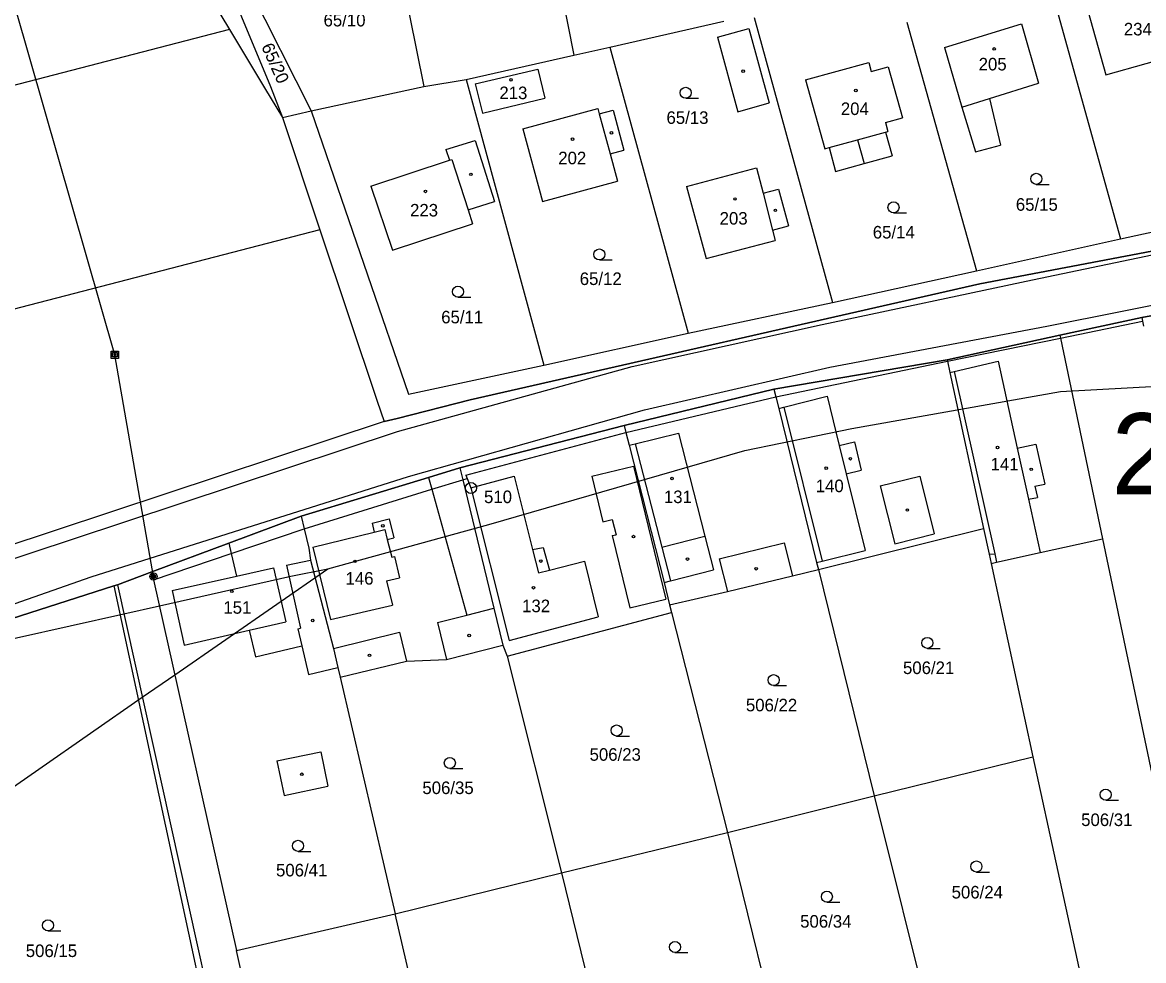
# Model space of a CAD drawing. Extents: x -725765 to -723182, y -1052705 to -1049154.
# Drawn here: x -724986 to -724834.1, y -1051208.1 to -1051081 of the extents above; entities that cross this region are included whole.
import ezdxf

# ---------------------------------------------------------------- set-up
doc = ezdxf.new("R2010")
doc.units = 0
for name, color, linetype in [('Vrstva 1', 7, 'Continuous'), ('Vrstva 12', 7, 'Continuous'), ('Vrstva 17', 7, 'Continuous'), ('Vrstva 18', 7, 'Continuous'), ('Vrstva 19', 7, 'Continuous'), ('Vrstva 25', 7, 'Continuous'), ('Vrstva 4', 7, 'Continuous'), ('Vrstva 52', 7, 'Continuous'), ('Vrstva 53', 7, 'Continuous')]:
    doc.layers.add(name, color=color, linetype=linetype)

msp = doc.modelspace()

# ---------------------------------------------------------------- linework, layer by layer
at = {"layer": 'Vrstva 1'}
for points in [[(-724918.87, -1051047.1), (-724911.27, -1051085.47)], [(-724939.3, -1051051.63), (-724931.61, -1051089.72)], [(-724963.58, -1051059.89), (-724946.87, -1051092.99)], [(-724960.47, -1051070.23), (-724952.37, -1051089.69)], [(-724964.46, -1051071.2), (-724957.95, -1051081.99)], [(-724847.95, -1051071.78), (-724837.23, -1051110.34)], [(-724842.01, -1051078.13), (-724839.24, -1051088.1)], [(-724906.4, -1051084.35), (-724890.95, -1051080.83)], [(-724886.87, -1051080.34), (-724876.24, -1051118.93)], [(-724866.18, -1051080.99), (-724856.76, -1051114.67)], [(-724861.08, -1051084.41), (-724850.66, -1051081.22)], [(-724850.66, -1051081.22), (-724848.32, -1051089.26)], [(-724957.95, -1051081.99), (-725181.44, -1051139.93)], [(-724957.95, -1051081.99), (-724953.19, -1051089.88), (-724950.77, -1051093.89)], [(-724911.27, -1051085.47), (-724906.4, -1051084.35)], [(-724906.4, -1051084.35), (-724895.82, -1051123.1)], [(-724925.9, -1051088.74), (-724911.27, -1051085.47)], [(-724861.08, -1051084.41), (-724858.73, -1051092.49)], [(-724839.24, -1051088.1), (-724828.29, -1051085.04)], [(-724924.64, -1051089.34), (-724916.16, -1051087.33)], [(-724916.16, -1051087.33), (-724915.23, -1051091.27)], [(-724879.9, -1051088.81), (-724871.34, -1051086.45)], [(-724871.34, -1051086.45), (-724871.02, -1051087.66)], [(-724871.02, -1051087.66), (-724868.72, -1051087.05)], [(-724868.72, -1051087.05), (-724866.77, -1051093.94)], [(-724931.61, -1051089.72), (-724925.9, -1051088.74)], [(-724925.9, -1051088.74), (-724915.34, -1051127.42)], [(-724879.9, -1051088.81), (-724877.3, -1051098.14)], [(-724952.37, -1051089.69), (-724950.77, -1051093.89)], [(-724946.87, -1051092.99), (-724931.61, -1051089.72)], [(-724924.64, -1051089.34), (-724923.67, -1051093.3)], [(-724855, -1051091.33), (-724848.32, -1051089.26)], [(-724923.67, -1051093.3), (-724915.23, -1051091.27)], [(-724855, -1051091.33), (-724853.47, -1051097.65)], [(-724950.77, -1051093.89), (-724946.87, -1051092.99)], [(-724946.87, -1051092.99), (-724939.23, -1051115.22)], [(-724918.18, -1051095.44), (-724908.03, -1051092.69)], [(-724908.03, -1051092.69), (-724907.84, -1051093.4)], [(-724907.84, -1051093.4), (-724905.98, -1051092.9)], [(-724905.98, -1051092.9), (-724904.5, -1051098.32)], [(-724858.73, -1051092.49), (-724856.88, -1051098.54)], [(-724950.77, -1051093.89), (-724945.68, -1051109.11)], [(-724869.09, -1051094.58), (-724866.77, -1051093.94)], [(-724869.09, -1051094.58), (-724868.76, -1051095.79)], [(-724918.18, -1051095.44), (-724915.53, -1051105.26)], [(-724869.05, -1051095.87), (-724868.76, -1051095.79)], [(-724869.05, -1051095.87), (-724868.17, -1051099.08)], [(-724928.62, -1051098.25), (-724924.67, -1051097.02)], [(-724924.67, -1051097.02), (-724922.03, -1051105.26)], [(-724877.3, -1051098.14), (-724876.72, -1051097.98)], [(-724876.72, -1051097.98), (-724875.84, -1051101.19)], [(-724856.88, -1051098.54), (-724853.47, -1051097.65)], [(-724928.62, -1051098.25), (-724928.15, -1051099.69)], [(-724906.36, -1051098.82), (-724904.5, -1051098.32)], [(-724906.36, -1051098.82), (-724905.36, -1051102.51)], [(-724871.98, -1051100.13), (-724868.17, -1051099.08)], [(-724938.78, -1051103.21), (-724928.15, -1051099.69)], [(-724896.03, -1051103.25), (-724886.54, -1051100.73)], [(-724886.54, -1051100.73), (-724885.65, -1051104.15)], [(-724875.84, -1051101.19), (-724871.98, -1051100.13)], [(-724915.53, -1051105.26), (-724905.36, -1051102.51)], [(-724938.78, -1051103.21), (-724935.84, -1051111.84)], [(-724896.03, -1051103.25), (-724893.36, -1051113.01)], [(-724885.65, -1051104.15), (-724883.57, -1051103.6)], [(-724883.57, -1051103.6), (-724882.22, -1051108.57)], [(-724925.59, -1051106.41), (-724922.03, -1051105.26)], [(-724925.59, -1051106.41), (-724925, -1051108.28)], [(-724837.23, -1051110.34), (-724817.68, -1051106.09)], [(-724935.84, -1051111.84), (-724925, -1051108.28)], [(-724884.36, -1051109.16), (-724882.22, -1051108.57)], [(-724945.68, -1051109.11), (-725175.46, -1051168.68)], [(-724945.68, -1051109.11), (-724937.92, -1051132.29)], [(-724884.36, -1051109.16), (-724884, -1051110.53)], [(-724856.27, -1051116.41), (-724816.84, -1051108.91)], [(-724893.36, -1051113.01), (-724884, -1051110.53)], [(-724856.76, -1051114.67), (-724837.23, -1051110.34)], [(-724876.24, -1051118.93), (-724856.76, -1051114.67)], [(-724939.23, -1051115.22), (-724933.68, -1051131.38)], [(-724925.34, -1051132.13), (-724856.27, -1051116.41)], [(-724834.36, -1051120.96), (-724811.15, -1051116.69)], [(-724895.82, -1051123.1), (-724876.24, -1051118.93)], [(-724845.44, -1051123.38), (-724834.36, -1051120.96)], [(-724834.36, -1051120.96), (-724834.26, -1051121.49)], [(-724834.26, -1051121.49), (-724834.1, -1051122.17)], [(-724915.34, -1051127.42), (-724895.82, -1051123.1)], [(-724860.72, -1051126.71), (-724845.44, -1051123.38)], [(-724845.44, -1051123.38), (-724845.36, -1051123.76)], [(-724845.36, -1051123.76), (-724839.66, -1051150.93)], [(-724884.18, -1051130.69), (-724860.72, -1051126.71)], [(-724860.72, -1051126.71), (-724860.68, -1051126.9)], [(-724860.68, -1051126.9), (-724860.35, -1051128.42)], [(-724933.68, -1051131.38), (-724915.34, -1051127.42)], [(-724860.35, -1051128.42), (-724855.78, -1051149.55)], [(-724904.47, -1051135.61), (-724884.18, -1051130.69)], [(-724884.18, -1051130.69), (-724883.92, -1051131.73)], [(-724937.92, -1051132.29), (-724936.98, -1051135.08)], [(-724935.23, -1051134.64), (-724925.34, -1051132.13)], [(-724883.92, -1051131.73), (-724883.54, -1051133.28)], [(-724883.54, -1051133.28), (-724878.4, -1051154.14)], [(-724936.98, -1051135.08), (-725011.19, -1051159.63)], [(-724936.98, -1051135.08), (-724935.23, -1051134.64)], [(-724926.75, -1051141.34), (-724904.47, -1051135.61)], [(-724904.47, -1051135.61), (-724904.23, -1051136.57)], [(-724904.23, -1051136.57), (-724903.79, -1051138.28)], [(-724903.79, -1051138.28), (-724899.07, -1051156.87)], [(-724930.97, -1051142.63), (-724926.75, -1051141.34)], [(-724926.75, -1051141.34), (-724926.34, -1051142.94)], [(-724948.22, -1051147.9), (-724930.97, -1051142.63)], [(-724930.97, -1051142.63), (-724930.52, -1051144.24)], [(-724926.34, -1051142.94), (-724922.12, -1051160.36)], [(-724930.52, -1051144.24), (-724925.8, -1051161.28)], [(-724958.02, -1051151.55), (-724948.22, -1051147.9)], [(-724948.22, -1051147.9), (-724947.82, -1051149.61)], [(-724947.82, -1051149.61), (-724947.2, -1051152.23)], [(-724878.16, -1051155.11), (-724855.78, -1051149.55)], [(-724855.78, -1051149.55), (-724855.03, -1051153.04)], [(-724848.12, -1051152.8), (-724839.66, -1051150.93)], [(-724839.66, -1051150.93), (-724823.81, -1051226.41)], [(-724968.47, -1051155.44), (-724958.02, -1051151.55)], [(-724958.02, -1051151.55), (-724957.7, -1051152.94)], [(-724947.2, -1051152.23), (-724946.95, -1051153.82)], [(-724957.7, -1051152.94), (-724956.98, -1051156)], [(-724946.95, -1051153.82), (-724943.87, -1051165.78)], [(-724878.4, -1051154.14), (-724878.16, -1051155.11)], [(-724855.03, -1051153.04), (-724854.76, -1051154.27)], [(-724854.76, -1051154.27), (-724854.01, -1051154.1)], [(-724854.01, -1051154.1), (-724848.12, -1051152.8)], [(-724973.12, -1051157.17), (-724968.47, -1051155.44)], [(-724968.47, -1051155.44), (-724968.23, -1051156.49)], [(-724881.69, -1051155.97), (-724878.16, -1051155.11)], [(-724878.16, -1051155.11), (-724870.61, -1051185.73)], [(-724854.76, -1051154.27), (-724849.09, -1051180.48)], [(-724973.59, -1051157.32), (-724973.12, -1051157.17)], [(-724973.12, -1051157.17), (-724950.33, -1051260.17)], [(-724968.23, -1051156.49), (-724956.97, -1051206.71)], [(-724965.73, -1051157.96), (-724956.98, -1051156)], [(-724899.07, -1051156.87), (-724898.31, -1051159.87)], [(-724890.48, -1051158.09), (-724881.69, -1051155.97)], [(-725009.19, -1051168.73), (-724973.59, -1051157.32)], [(-724965.73, -1051157.96), (-724964.09, -1051165.34)], [(-724898.31, -1051159.87), (-724890.48, -1051158.09)], [(-724898.31, -1051159.87), (-724898.04, -1051160.94)], [(-724929.77, -1051162.27), (-724925.8, -1051161.28)], [(-724922.12, -1051160.36), (-724920.89, -1051165.34)], [(-724920.33, -1051166.83), (-724898.04, -1051160.94)], [(-724898.04, -1051160.94), (-724890.47, -1051190.71)], [(-724964.09, -1051165.34), (-724955.27, -1051163.31)], [(-724955.27, -1051163.31), (-724954.44, -1051166.92)], [(-724929.77, -1051162.27), (-724928.52, -1051167.28)], [(-724954.44, -1051166.92), (-724948.14, -1051165.46)], [(-724948.14, -1051165.46), (-724947.23, -1051169.32)], [(-724943.87, -1051165.78), (-724943.27, -1051168.39)], [(-724920.89, -1051165.34), (-724920.33, -1051166.83)], [(-724942.93, -1051169.69), (-724933.97, -1051167.53)], [(-724933.97, -1051167.53), (-724928.52, -1051167.28)], [(-724920.33, -1051166.83), (-724912.94, -1051196.18)], [(-724947.23, -1051169.32), (-724943.27, -1051168.39)], [(-724943.27, -1051168.39), (-724942.93, -1051169.69)], [(-724942.93, -1051169.69), (-724935.5, -1051201.73)], [(-724870.61, -1051185.73), (-724849.09, -1051180.48)], [(-724849.09, -1051180.48), (-724842.32, -1051211.51)], [(-724890.47, -1051190.71), (-724870.61, -1051185.73)], [(-724870.61, -1051185.73), (-724862.89, -1051216.71)], [(-724912.94, -1051196.18), (-724890.47, -1051190.71)], [(-724890.47, -1051190.71), (-724882.37, -1051223.57)], [(-724935.5, -1051201.73), (-724912.94, -1051196.18)], [(-724912.94, -1051196.18), (-724905.17, -1051228.09)], [(-724956.97, -1051206.71), (-724935.5, -1051201.73)], [(-724929.66, -1051226.78), (-724935.5, -1051201.73)], [(-724951.47, -1051231.54), (-724956.97, -1051206.71)]]:
    msp.add_lwpolyline(points, dxfattribs=at)
at = {"layer": 'Vrstva 12'}
for points in [[(-724973.47, -1051126.02), (-724988.81, -1051072.44)], [(-724968.25, -1051156.05), (-724973.47, -1051126.02)]]:
    msp.add_lwpolyline(points, dxfattribs=at)
at = {"layer": 'Vrstva 25'}
for points in [[(-724896.13, -1051091.3), (-724894.38, -1051091.3)], [(-724848.64, -1051102.95), (-724846.89, -1051102.95)], [(-724867.98, -1051106.81), (-724866.23, -1051106.81)], [(-724907.83, -1051113.19), (-724906.08, -1051113.19)], [(-724926.99, -1051118.24), (-724925.24, -1051118.24)], [(-724973.97, -1051125.52), (-724972.97, -1051125.52), (-724972.97, -1051126.52), (-724973.97, -1051126.52), (-724973.97, -1051125.52)], [(-724973.77, -1051125.72), (-724973.17, -1051125.72), (-724973.17, -1051126.32), (-724973.77, -1051126.32), (-724973.77, -1051125.72)], [(-724973.57, -1051125.92), (-724973.37, -1051125.92), (-724973.37, -1051126.12), (-724973.57, -1051126.12), (-724973.57, -1051125.92)], [(-724863.4, -1051165.79), (-724861.65, -1051165.79)], [(-724884.23, -1051170.83), (-724882.48, -1051170.83)], [(-724905.49, -1051177.65), (-724903.74, -1051177.65)], [(-724928.09, -1051182.05), (-724926.34, -1051182.05)], [(-724839.24, -1051186.34), (-724837.49, -1051186.34)], [(-724948.65, -1051193.27), (-724946.9, -1051193.27)], [(-724856.75, -1051196.07), (-724855, -1051196.07)], [(-724877.01, -1051200.16), (-724875.26, -1051200.16)], [(-724982.54, -1051204.04), (-724980.79, -1051204.04)], [(-724897.59, -1051206.97), (-724895.84, -1051206.97)]]:
    msp.add_lwpolyline(points, dxfattribs=at)
for centre, radius in [((-724854.35, -1051084.61), 0.175), ((-724919.8, -1051088.79), 0.175), ((-724888.35, -1051087.63), 0.175), ((-724896.13, -1051090.55), 0.75), ((-724873.08, -1051090.25), 0.175), ((-724906.2, -1051095.97), 0.175), ((-724911.46, -1051096.84), 0.175), ((-724925.23, -1051101.59), 0.175), ((-724848.64, -1051102.2), 0.75), ((-724931.4, -1051103.9), 0.175), ((-724889.46, -1051104.93), 0.175), ((-724867.98, -1051106.06), 0.75), ((-724883.99, -1051106.47), 0.175), ((-724907.83, -1051112.44), 0.75), ((-724926.99, -1051117.49), 0.75), ((-724853.88, -1051138.59), 0.175), ((-724873.83, -1051140.1), 0.175), ((-724877.09, -1051141.39), 0.175), ((-724849.32, -1051141.54), 0.175), ((-724925.23, -1051144.06), 0.75), ((-724897.99, -1051142.77), 0.175), ((-724925.23, -1051144.06), 0.032), ((-724866.11, -1051147.05), 0.175), ((-724937.16, -1051149.18), 0.175), ((-724903.2, -1051150.65), 0.175), ((-724940.94, -1051154), 0.175), ((-724915.76, -1051153.96), 0.175), ((-724895.9, -1051153.69), 0.175), ((-724968.25, -1051156.05), 0.5), ((-724968.25, -1051156.05), 0.3), ((-724886.58, -1051155), 0.175), ((-724968.25, -1051156.05), 0.15), ((-724957.61, -1051158.05), 0.175), ((-724916.75, -1051157.57), 0.175), ((-724946.67, -1051162), 0.175), ((-724925.47, -1051164.03), 0.175), ((-724863.4, -1051165.04), 0.75), ((-724938.97, -1051166.73), 0.175), ((-724884.23, -1051170.08), 0.75), ((-724905.49, -1051176.9), 0.75), ((-724928.09, -1051181.3), 0.75), ((-724948.14, -1051182.83), 0.175), ((-724839.24, -1051185.59), 0.75), ((-724948.65, -1051192.52), 0.75), ((-724856.75, -1051195.32), 0.75), ((-724877.01, -1051199.41), 0.75), ((-724982.54, -1051203.29), 0.75), ((-724897.59, -1051206.22), 0.75)]:
    msp.add_circle(centre, radius, dxfattribs=at)
at = {"layer": 'Vrstva 4'}
for points in [[(-724891.81, -1051083.01), (-724887.57, -1051081.86)], [(-724887.57, -1051081.86), (-724884.83, -1051091.93)], [(-724891.81, -1051083.01), (-724889.06, -1051093.11)], [(-724889.06, -1051093.11), (-724884.83, -1051091.93)], [(-724858.73, -1051092.49), (-724855, -1051091.33)], [(-724907.84, -1051093.4), (-724906.36, -1051098.82)], [(-724872.86, -1051096.92), (-724869.05, -1051095.87)], [(-724876.72, -1051097.98), (-724872.86, -1051096.92)], [(-724872.86, -1051096.92), (-724871.98, -1051100.13)], [(-724928.15, -1051099.69), (-724927.81, -1051099.58)], [(-724927.81, -1051099.58), (-724925.59, -1051106.41)], [(-724885.65, -1051104.15), (-724884.36, -1051109.16)], [(-724849.16, -1051115.88), (-724818.67, -1051109.51)], [(-724877.64, -1051121.92), (-724849.16, -1051115.88)], [(-724847.23, -1051122.13), (-724816.84, -1051116.09)], [(-724903.4, -1051127.62), (-724877.64, -1051121.92)], [(-724876.62, -1051127.71), (-724847.23, -1051122.13)], [(-724845.36, -1051123.76), (-724834.26, -1051121.49)], [(-724860.68, -1051126.9), (-724845.36, -1051123.76)], [(-724883.92, -1051131.73), (-724860.68, -1051126.9)], [(-724859.76, -1051128.28), (-724853.79, -1051126.9)], [(-724853.79, -1051126.9), (-724851.21, -1051138.68)], [(-724935.17, -1051136.41), (-724903.4, -1051127.62)], [(-724901.71, -1051133.46), (-724876.62, -1051127.71)], [(-724860.35, -1051128.42), (-724859.76, -1051128.28)], [(-724859.76, -1051128.28), (-724854.26, -1051152.99)], [(-724904.23, -1051136.57), (-724883.92, -1051131.73)], [(-724882.84, -1051133.11), (-724876.98, -1051131.64)], [(-724876.98, -1051131.64), (-724875.33, -1051138.32)], [(-724933.69, -1051142.51), (-724901.71, -1051133.46)], [(-724883.54, -1051133.28), (-724882.84, -1051133.11)], [(-724882.84, -1051133.11), (-724877.67, -1051153.96)], [(-724979.2, -1051151.01), (-724935.17, -1051136.41)], [(-724925.91, -1051142.34), (-724904.23, -1051136.57)], [(-724902.97, -1051138.08), (-724897.1, -1051136.62)], [(-724897.1, -1051136.62), (-724893.53, -1051150.58)], [(-724903.79, -1051138.28), (-724902.97, -1051138.08)], [(-724902.97, -1051138.08), (-724899.38, -1051152.06)], [(-724875.33, -1051138.32), (-724873.28, -1051137.82)], [(-724875.33, -1051138.32), (-724874.39, -1051142.15)], [(-724873.28, -1051137.82), (-724872.37, -1051141.63)], [(-724851.21, -1051138.68), (-724848.69, -1051138.14)], [(-724851.21, -1051138.68), (-724849.7, -1051145.6)], [(-724848.69, -1051138.14), (-724847.5, -1051143.53)], [(-724908.86, -1051142.48), (-724903.23, -1051141.09)], [(-724903.23, -1051141.09), (-724898.84, -1051159.11)], [(-724874.39, -1051142.15), (-724872.37, -1051141.63)], [(-724976.7, -1051156.09), (-724933.69, -1051142.51)], [(-724930.52, -1051144.24), (-724926.34, -1051142.94)], [(-724926.34, -1051142.94), (-724925.76, -1051142.78)], [(-724925.91, -1051142.34), (-724925.76, -1051142.78)], [(-724925.76, -1051142.78), (-724925.23, -1051144.06)], [(-724925.23, -1051144.06), (-724919.36, -1051142.48)], [(-724919.36, -1051142.48), (-724916.87, -1051152.4)], [(-724908.86, -1051142.48), (-724907.35, -1051148.63)], [(-724874.39, -1051142.15), (-724871.84, -1051152.51)], [(-724869.78, -1051143.75), (-724864.43, -1051142.45)], [(-724864.43, -1051142.45), (-724862.48, -1051150.29)], [(-724848.82, -1051143.82), (-724847.5, -1051143.53)], [(-724947.82, -1051149.61), (-724930.52, -1051144.24)], [(-724925.23, -1051144.06), (-724920.07, -1051164.7)], [(-724869.78, -1051143.75), (-724867.82, -1051151.62)], [(-724848.82, -1051143.82), (-724848.47, -1051145.36)], [(-724849.7, -1051145.6), (-724848.47, -1051145.36)], [(-724849.7, -1051145.6), (-724848.12, -1051152.8)], [(-724957.7, -1051152.94), (-724947.82, -1051149.61)], [(-724938.63, -1051148.81), (-724936.33, -1051148.26)], [(-724938.63, -1051148.81), (-724938.32, -1051150.05)], [(-724936.33, -1051148.26), (-724935.69, -1051150.83)], [(-724907.35, -1051148.63), (-724906.08, -1051148.32)], [(-724906.08, -1051148.32), (-724905.57, -1051150.39)], [(-725010.8, -1051161.4), (-724979.2, -1051151.01)], [(-724946.63, -1051152.09), (-724938.32, -1051150.05)], [(-724938.32, -1051150.05), (-724936.91, -1051149.7)], [(-724936.91, -1051149.7), (-724936.57, -1051151.06)], [(-724936.57, -1051151.06), (-724935.69, -1051150.83)], [(-724936.57, -1051151.06), (-724935.96, -1051153.45)], [(-724906.11, -1051150.52), (-724905.57, -1051150.39)], [(-724906.11, -1051150.52), (-724903.7, -1051160.31)], [(-724899.38, -1051152.06), (-724893.53, -1051150.58)], [(-724893.53, -1051150.58), (-724892.36, -1051155.16)], [(-724867.82, -1051151.62), (-724862.48, -1051150.29)], [(-724946.63, -1051152.09), (-724944.25, -1051161.89)], [(-724916.87, -1051152.4), (-724915.43, -1051152.11)], [(-724916.87, -1051152.4), (-724916.07, -1051155.57)], [(-724915.43, -1051152.11), (-724914.6, -1051155.19)], [(-724899.38, -1051152.06), (-724898.2, -1051156.65)], [(-724891.59, -1051153.66), (-724882.8, -1051151.48)], [(-724882.8, -1051151.48), (-724881.69, -1051155.97)], [(-724877.67, -1051153.96), (-724871.84, -1051152.51)], [(-724968.23, -1051156.49), (-724957.7, -1051152.94)], [(-724950.21, -1051154.52), (-724946.95, -1051153.82)], [(-724935.96, -1051153.45), (-724935.6, -1051153.36)], [(-724935.6, -1051153.36), (-724934.89, -1051156.22)], [(-724914.6, -1051155.19), (-724909.84, -1051153.96)], [(-724909.84, -1051153.96), (-724907.99, -1051161.51)], [(-724891.59, -1051153.66), (-724890.48, -1051158.09)], [(-724878.4, -1051154.14), (-724877.67, -1051153.96)], [(-724855.03, -1051153.04), (-724854.26, -1051152.99)], [(-724854.26, -1051152.99), (-724854.01, -1051154.1)], [(-724956.98, -1051156), (-724951.97, -1051154.88)], [(-724951.97, -1051154.88), (-724950.31, -1051162.17)], [(-724950.21, -1051154.52), (-724948.3, -1051163.03)], [(-724916.07, -1051155.57), (-724914.6, -1051155.19)], [(-724898.2, -1051156.65), (-724892.36, -1051155.16)], [(-725009.44, -1051167.57), (-724976.7, -1051156.09)], [(-724936.67, -1051156.65), (-724934.89, -1051156.22)], [(-724936.67, -1051156.65), (-724935.87, -1051159.94)], [(-724899.07, -1051156.87), (-724898.2, -1051156.65)], [(-724973.59, -1051157.32), (-724951.45, -1051260.42)], [(-724944.25, -1051161.89), (-724935.87, -1051159.94)], [(-724903.7, -1051160.31), (-724898.84, -1051159.11)], [(-724925.8, -1051161.28), (-724922.12, -1051160.36)], [(-724920.07, -1051164.7), (-724907.99, -1051161.51)], [(-724955.27, -1051163.31), (-724950.31, -1051162.17)], [(-724948.69, -1051163.12), (-724948.3, -1051163.03)], [(-724948.69, -1051163.12), (-724948.14, -1051165.46)], [(-724943.87, -1051165.78), (-724934.91, -1051163.59)], [(-724934.91, -1051163.59), (-724933.97, -1051167.53)], [(-724928.52, -1051167.28), (-724920.89, -1051165.34)], [(-724951.52, -1051181.01), (-724945.58, -1051179.79)], [(-724945.58, -1051179.79), (-724944.64, -1051184.45)], [(-724951.52, -1051181.01), (-724950.54, -1051185.7)], [(-724950.54, -1051185.7), (-724944.64, -1051184.45)]]:
    msp.add_lwpolyline(points, dxfattribs=at)
at = {"layer": 'Vrstva 52'}
for points in [[(-724711.14, -1051080.07), (-724811.24, -1051105.56), (-724810.03, -1051107.31), (-724816.84, -1051108.91), (-724856.27, -1051116.41), (-724925.34, -1051132.13), (-724935.23, -1051134.64), (-724936.98, -1051135.08), (-725011.19, -1051159.63), (-725057.43, -1051172.97), (-725105.34, -1051186.54), (-725152.07, -1051199.14), (-725159.2, -1051200.55), (-725166.37, -1051202.6), (-725179.86, -1051206.45), (-725205.38, -1051213.74), (-725231.72, -1051221.15), (-725243.81, -1051225.51), (-725272.4, -1051235.81), (-725277.83, -1051237.87), (-725301.81, -1051246.05), (-725340.64, -1051260.21)], [(-724738.66, -1051101.7), (-724743.22, -1051102.61), (-724765.92, -1051107.34), (-724788.6, -1051112.06), (-724811.15, -1051116.69), (-724834.36, -1051120.96), (-724845.44, -1051123.38), (-724860.72, -1051126.71), (-724884.18, -1051130.69), (-724904.47, -1051135.61), (-724926.75, -1051141.34), (-724930.97, -1051142.63), (-724948.22, -1051147.9), (-724958.02, -1051151.55), (-724968.47, -1051155.44), (-724973.12, -1051157.17), (-724973.59, -1051157.32), (-725009.19, -1051168.73), (-725008.93, -1051169.9)], [(-724944.63, -1051155), (-724922.81, -1051149), (-724888.13, -1051139), (-724873.63, -1051136), (-724845.38, -1051131), (-724827.31, -1051130), (-724796.88, -1051124), (-724758.63, -1051111)], [(-725008.93, -1051169.9), (-725008.66, -1051171.13), (-725000, -1051168.07), (-724994.13, -1051166), (-724972.25, -1051161.09), (-724967.44, -1051160), (-724949.63, -1051156), (-724944.63, -1051155)], [(-724990.81, -1051187), (-724969.75, -1051172.41), (-724965.35, -1051169.36), (-724944.63, -1051155)]]:
    msp.add_lwpolyline(points, dxfattribs=at)

# ---------------------------------------------------------------- texts
at = {"layer": 'Vrstva 17'}
msp.add_text('510', height=1.7, dxfattribs=at).set_placement((-724923.46, -1051146.11))
at = {"layer": 'Vrstva 18'}
for s, p in [('65/10', (-724945.2, -1051081.56)), ('65/13', (-724898.74, -1051094.76)), ('65/15', (-724851.41, -1051106.52)), ('65/14', (-724870.79, -1051110.28)), ('65/12', (-724910.49, -1051116.58)), ('65/11', (-724929.26, -1051121.77)), ('506/21', (-724866.7, -1051169.26)), ('506/22', (-724887.98, -1051174.31)), ('506/23', (-724909.16, -1051181)), ('506/35', (-724931.81, -1051185.51)), ('506/31', (-724842.56, -1051189.84)), ('506/41', (-724951.64, -1051196.66)), ('506/24', (-724860.11, -1051199.65)), ('506/34', (-724880.63, -1051203.6)), ('506/15', (-724985.54, -1051207.58))]:
    msp.add_text(s, height=1.7, dxfattribs=at).set_placement(p)
msp.add_text('65/20', height=1.7, rotation=294.1023, dxfattribs=at).set_placement((-724953.67, -1051084.28))
at = {"layer": 'Vrstva 19'}
for s, p in [('234', (-724836.78, -1051082.78)), ('205', (-724856.45, -1051087.52)), ('213', (-724921.38, -1051091.41)), ('204', (-724875.12, -1051093.56)), ('202', (-724913.4, -1051100.23)), ('223', (-724933.48, -1051107.3)), ('203', (-724891.54, -1051108.4)), ('141', (-724854.83, -1051141.69)), ('140', (-724878.52, -1051144.63)), ('131', (-724899.09, -1051146.11)), ('146', (-724942.22, -1051157.15)), ('151', (-724958.77, -1051161.09)), ('132', (-724918.3, -1051160.88))]:
    msp.add_text(s, height=1.7, dxfattribs=at).set_placement(p)
at = {"layer": 'Vrstva 53'}
msp.add_text('21000', height=11, dxfattribs=at).set_placement((-724838.44, -1051144.94))

doc.saveas('drawing.dxf')
